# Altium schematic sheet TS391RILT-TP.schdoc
size 127 x 101 mm
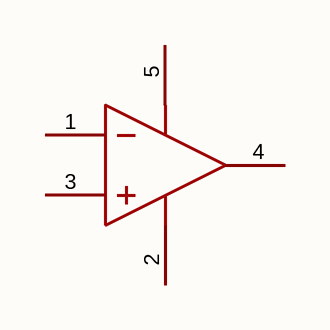
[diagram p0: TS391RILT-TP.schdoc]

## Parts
U?  ts391rilt-tp  [SOT-23-5_L3.0-W1.5-P0.95-LS2.8-BL]  (value not drawn)

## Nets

Not connected (* = marked no-connect by the designer): U? 1(IN-) 2(gnd) 3(IN+) 4(OUT) 5(VCC+)

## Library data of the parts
U? = ts391rilt-tp: 比较器数:单路;输入失调电压(Vos):2mV;输入偏置电流(Ib):25nA;; Manufacturer: TECH PUBLIC(台舟); AddInBom: yes; ModelId: 424d41c645fb4cc2a3598f66fad27964; ModelTransform: 118.11,110.236,0,0,0,0,0,0,0; Number of Channels: 单路; Vos - Input Offset Voltage: 2mV; Ib - Input Bias Current: 25nA; Propagation Delay Time: 300ns; Output Mode: MOS；CMOS；ECL；DTL；TTL; Quiescent Current: 400uA; Maximum Power Supply Range (Vdd-Vss): 36V; Single Supply: 2V~36V; Dual Supply: -18V~-1V；1V~18V; Input Offset Current(Ios): 50nA; Response Time (tr): 1.3us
